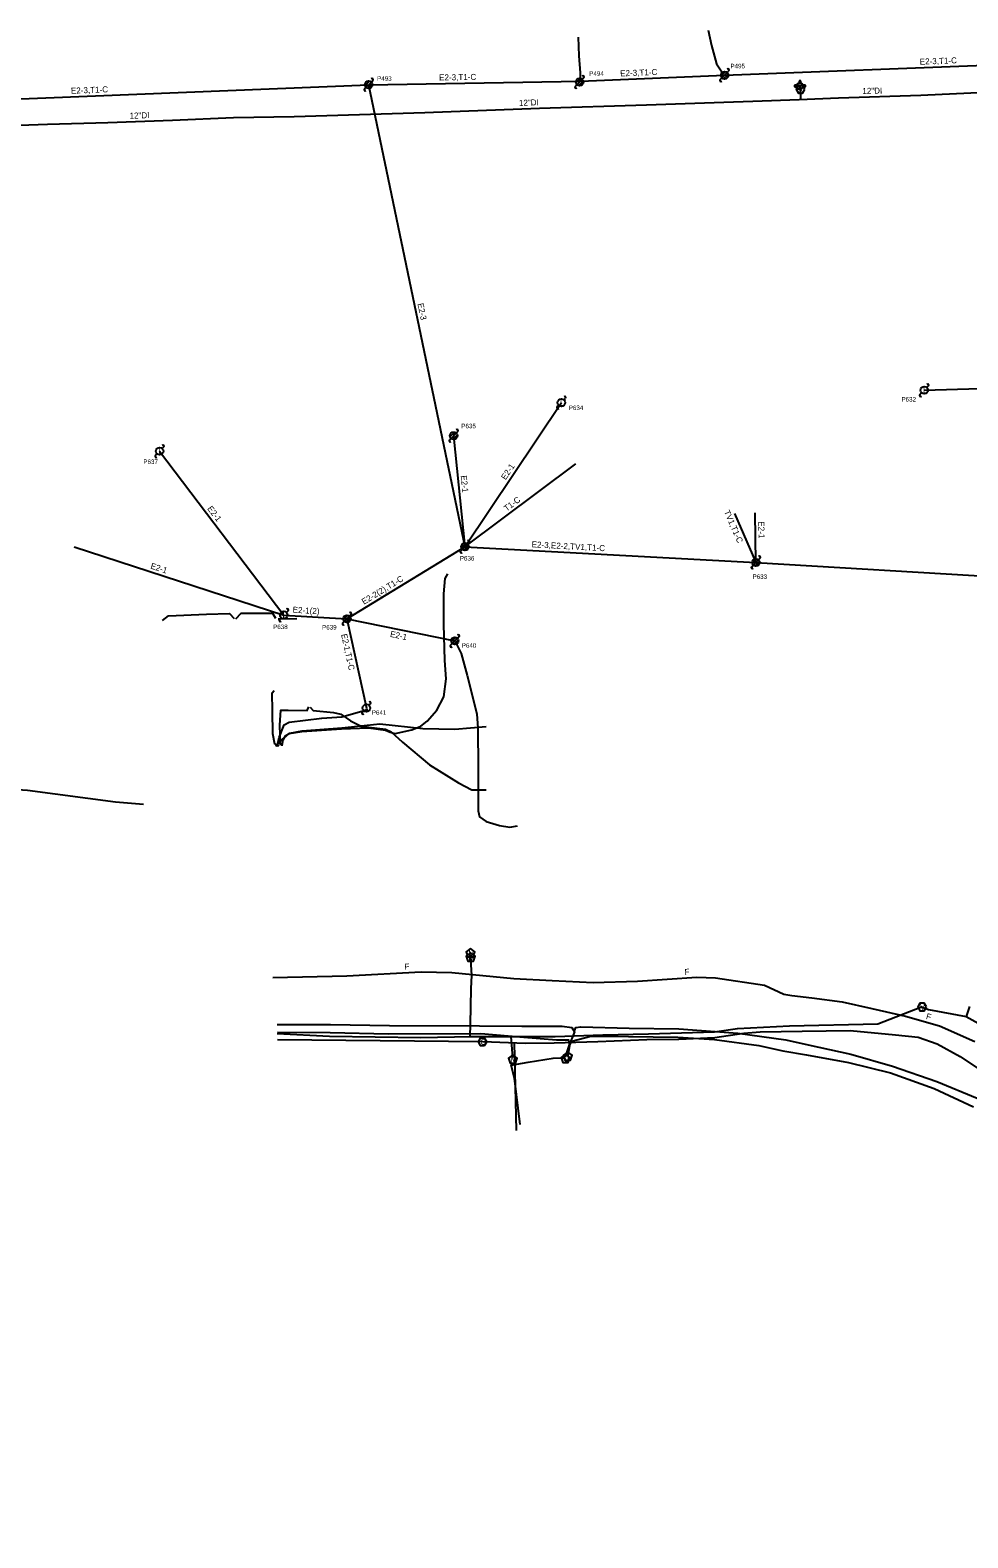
# Model space of a CAD drawing. Extents: x 1741604 to 1825760, y 1164229 to 1194908.
# Drawn here: x 1811075 to 1811697, y 1189297 to 1190297 of the extents above; entities that cross this region are included whole.
import ezdxf

# ---------------------------------------------------------------- set-up
doc = ezdxf.new("R2010")
doc.units = 0
for name, color, linetype in [('RD_EX_SU_Elec', 7, 'Continuous'), ('RD_EX_SU_Gas', 7, 'Continuous'), ('RD_EX_SU_H2O', 7, 'Continuous'), ('RD_EX_SU_Ovhd', 7, 'Continuous'), ('RD_EX_SU_Pole', 7, 'Continuous'), ('RD_EX_SU_Telecom', 7, 'Continuous'), ('RD_EX_SU_TX_H2O', 7, 'Continuous'), ('RD_EX_SU_TX_Pole', 7, 'Continuous'), ('RD_EX_SU_TX_Telecom', 7, 'Continuous')]:
    doc.layers.add(name, color=color, linetype=linetype)

# ---------------------------------------------------------------- blocks, each defined once
blk = doc.blocks.new('SUE_WV')
at = {"layer": 'RD_EX_SU_H2O'}
blk.add_lwpolyline([(2.9, 0), (1.4, 2.5), (-1.4, 2.5), (-2.9, 0), (-1.4, -2.5), (1.4, -2.5)], close=True, dxfattribs=at)
blk.add_text('V', height=3.75, dxfattribs=at).set_placement((-1.4, -1.9))
blk = doc.blocks.new('SUE_WFH')
at = {"layer": 'RD_EX_SU_H2O'}
for p, q in [((-2, 0.6), (-3.6, 0.6)), ((-3.6, 0.6), (-3.6, -0.4)), ((-0.5, 3.4), (-0.5, 2)), ((0.6, 3.4), (-0.5, 3.4)), ((0.6, 2), (0.6, 3.4)), ((3.7, 0.6), (2, 0.6)), ((3.7, -0.4), (3.7, 0.6)), ((-3.6, -0.4), (-2.1, -0.4)), ((2.1, -0.4), (3.7, -0.4))]:
    blk.add_line(p, q, dxfattribs=at)
for radius in [2.1, 0.263]:
    blk.add_circle((0, 0), radius, dxfattribs=at)
for start, end in [(163.3387, 192.315), (74.2455, 103.2128), (347.685, 16.6613)]:
    blk.add_arc((0, 0), 2.1, start, end, dxfattribs=at)
blk = doc.blocks.new('SUE_PP')
at = {"layer": 'RD_EX_SU_Pole'}
for p, q in [((-2.4, -0.6), (0.6, 2.4)), ((-1.8, -1.8), (1.8, 1.8)), ((-0.6, -2.4), (2.4, 0.6)), ((1.8, 1.8), (2.8, 2.8)), ((-2.8, -2.8), (-1.8, -1.8))]:
    blk.add_line(p, q, dxfattribs=at)
blk.add_circle((0, 0), 2.5, dxfattribs=at)
for centre, start, end in [((2.3, 3.4), 315, 135), ((-2.3, -3.4), 135, 315)]:
    blk.add_arc(centre, 0.75, start, end, dxfattribs=at)
blk = doc.blocks.new('SUE_TPP')
at = {"layer": 'RD_EX_SU_Telecom'}
blk.add_lwpolyline([(0, 3), (-2.9, 0.9), (-1.8, -2.4), (1.8, -2.4), (2.9, 0.9)], close=True, dxfattribs=at)
blk.add_text('T', height=3.75, dxfattribs=at).set_placement((-1.3, -1.9))
blk = doc.blocks.new('SUE_GVC')
at = {"layer": 'RD_EX_SU_Gas'}
blk.add_lwpolyline([(1.4, -2.5), (2.9, 0), (1.4, 2.5), (-1.4, 2.5), (-2.9, 0), (-1.4, -2.5)], close=True, dxfattribs=at)
blk.add_text('G', height=3.75, dxfattribs=at).set_placement((-1.3, -1.9))
blk = doc.blocks.new('SUE_WM')
at = {"layer": 'RD_EX_SU_H2O'}
blk.add_lwpolyline([(0, 3.1), (-2.9, 0.9), (-1.8, -2.5), (1.8, -2.5), (2.9, 0.9)], close=True, dxfattribs=at)
blk.add_text('M', height=3.75, dxfattribs=at).set_placement((-1.4, -1.9))
blk = doc.blocks.new('SUE_TVP')
at = {"layer": 'RD_EX_SU_Telecom'}
blk.add_lwpolyline([(0, 3), (-2.9, 0.9), (-1.8, -2.4), (1.8, -2.4), (2.9, 0.9)], close=True, dxfattribs=at)
blk.add_text('C', height=4, dxfattribs=at).set_placement((-1.4, -2))

msp = doc.modelspace()

# ---------------------------------------------------------------- linework, layer by layer
at = {"layer": 'RD_EX_SU_Elec'}
msp.add_line((1811239.6, 1189906.8), (1811252, 1189907), dxfattribs=at)
for points in [[(1811438.7, 1190292.7), (1811439.3, 1190280.4), (1811440.1, 1190269.1), (1811440, 1190264.2)], [(1811162.9, 1189905.5), (1811166.9, 1189908.8), (1811192.2, 1189909.9), (1811207.4, 1189910.3), (1811210.4, 1189906.9)], [(1811211.5, 1189906.8), (1811215.1, 1189910.4), (1811235.9, 1189910.5), (1811237.8, 1189907.1)], [(1811357.2, 1189891.7), (1811361.2, 1189883.8), (1811365.2, 1189869.1), (1811371.4, 1189843.6), (1811372.2, 1189834.2), (1811372.3, 1189807.8), (1811372.5, 1189779.2), (1811373.3, 1189775.4), (1811377.7, 1189772.3), (1811386.5, 1189769.6), (1811393.4, 1189768.4), (1811398.4, 1189769.3)], [(1811240.1, 1189822.3), (1811237.4, 1189823.6), (1811236.2, 1189830.4), (1811235.9, 1189845.7), (1811235.6, 1189857.6), (1811237, 1189859.2)], [(1811238.9, 1189822), (1811240.4, 1189828), (1811243.6, 1189836.3), (1811247, 1189838.2), (1811268.7, 1189840.7), (1811268.7, 1189840.8), (1811281.9, 1189841.7), (1811295.3, 1189845.5), (1811299.2, 1189846.8)], [(1811241.2, 1189822.9), (1811240.8, 1189836.1), (1811241.4, 1189846), (1811246.3, 1189846), (1811258.9, 1189845.9), (1811260.1, 1189848.2)], [(1811260.9, 1189848.1), (1811263, 1189845.8), (1811276.4, 1189844.6), (1811281.2, 1189843.5), (1811287.6, 1189839), (1811295.2, 1189835.3), (1811299.8, 1189834.7), (1811310.8, 1189833.5), (1811314.6, 1189831.7), (1811322.1, 1189824.9), (1811340, 1189809.7), (1811359.4, 1189797.9), (1811368.2, 1189793.3), (1811377.8, 1189793.2)], [(1811242.4, 1189822.5), (1811242.9, 1189826.4), (1811244.6, 1189829.1), (1811247.3, 1189830.9), (1811255.6, 1189832.4), (1811281.9, 1189834.4), (1811307.2, 1189837), (1811335.7, 1189834), (1811356.8, 1189833.5), (1811377.7, 1189835.3)]]:
    msp.add_lwpolyline(points, dxfattribs=at)
at = {"layer": 'RD_EX_SU_Gas'}
for p, q in [((1811239.2, 1189627.6), (1811375.5, 1189626.2)), ((1811396.2, 1189625.4), (1811397.7, 1189567))]:
    msp.add_line(p, q, dxfattribs=at)
for points in [[(1810734.8, 1190009.3), (1810774, 1190011.4), (1810835.1, 1190017.5), (1810866.9, 1190019.3), (1810882.2, 1190019.5), (1810941.5, 1190020.8), (1811000.3, 1190023.5), (1811033.9, 1190028.1), (1811048.1, 1190029.3), (1811051.5, 1190009.5), (1811052.4, 1189991.2), (1811053.5, 1189936.5), (1811055, 1189888.8), (1811056.1, 1189830.6), (1811056.5, 1189794.2), (1811073.4, 1189793), (1811131.7, 1189785.3), (1811150.3, 1189783.6)], [(1811375.5, 1189626.2), (1811403.7, 1189625.1), (1811422.9, 1189625.3), (1811451.9, 1189626.2), (1811484.3, 1189627.4), (1811505.6, 1189627.7), (1811529.5, 1189628.9), (1811548.7, 1189631.8)], [(1811548.7, 1189631.8), (1811559.6, 1189632.5), (1811587.5, 1189633), (1811619.2, 1189633.4), (1811649.4, 1189630.7), (1811664.5, 1189629), (1811677.1, 1189624.6), (1811692.3, 1189616.2), (1811715.1, 1189600.9)]]:
    msp.add_lwpolyline(points, dxfattribs=at)
at = {"layer": 'RD_EX_SU_H2O'}
for p, q in [((1811586.6, 1190251.5), (1811586.2, 1190259.7)), ((1811395.3, 1189615.5), (1811394.4, 1189629.4))]:
    msp.add_line(p, q, dxfattribs=at)
for points in [[(1811043.2, 1190233.5), (1811086.6, 1190235.1), (1811126.7, 1190236.1), (1811169.6, 1190237.6), (1811210.1, 1190239.4), (1811250.3, 1190240.2), (1811337, 1190242.8), (1811413, 1190245.6), (1811484.1, 1190247.9), (1811554.6, 1190250.2), (1811585.4, 1190251.5), (1811611.5, 1190252.6), (1811666.2, 1190254.2), (1811727.8, 1190257.1), (1811744.5, 1190258.3), (1811751, 1190258.5), (1811790.7, 1190260.1), (1811828.8, 1190261.9)], [(1811367.1, 1189629.5), (1811367.3, 1189637.7), (1811367.8, 1189661.2), (1811368.2, 1189670.3), (1811367.4, 1189683.9)], [(1811239, 1189631.5), (1811273.7, 1189629.8), (1811334.4, 1189628.8), (1811367.8, 1189629.5), (1811395.3, 1189629.4), (1811423.5, 1189629.5), (1811455.1, 1189630.7), (1811485.5, 1189631.3), (1811529.3, 1189632.5), (1811544.4, 1189634.8), (1811578.9, 1189636.5), (1811637.6, 1189637.9), (1811666.5, 1189649.2), (1811671.3, 1189647.5), (1811696.3, 1189642.7)], [(1811698.4, 1189649.4), (1811696.3, 1189642.7), (1811716.1, 1189631.6), (1811727.3, 1189624.2), (1811740.2, 1189614.8), (1811756.2, 1189601.7), (1811776.4, 1189587.4), (1811783, 1189583.6), (1811800.8, 1189574.5), (1811834.9, 1189557.1), (1811855.9, 1189546.8), (1811878, 1189532.4), (1811893, 1189521.5), (1811927.7, 1189491.6), (1811968.1, 1189460.6), (1811979, 1189453.4), (1811992.9, 1189443.8), (1812013.5, 1189429.1), (1812036.1, 1189412.4), (1812055.6, 1189396.8), (1812100.9, 1189362.1), (1812129.5, 1189341.4), (1812152.6, 1189324.1), (1812186.1, 1189296.7)]]:
    msp.add_lwpolyline(points, dxfattribs=at)
at = {"layer": 'RD_EX_SU_Ovhd'}
for p, q in [((1811535.9, 1190267.5), (1811787.6, 1190277.2)), ((1811440.4, 1190263.6), (1811535.9, 1190267.5)), ((1810934.5, 1190246.4), (1811299.7, 1190261.2)), ((1811299.7, 1190261.2), (1811440.4, 1190263.6)), ((1811299.7, 1190261.2), (1811363.6, 1189954.6)), ((1811668.4, 1190058.5), (1811753.5, 1190061.2)), ((1811363.6, 1189954.6), (1811427.6, 1190050.2)), ((1811356.1, 1190028.2), (1811363.6, 1189954.6)), ((1811161, 1190018), (1811243.4, 1189909.2)), ((1811363.6, 1189954.6), (1811437.2, 1190009.5)), ((1811542.5, 1189976.7), (1811556.7, 1189944.1)), ((1811556.7, 1189944.1), (1811556.2, 1189977.1)), ((1811104.2, 1189954.4), (1811243.4, 1189909.2)), ((1811285.3, 1189906.7), (1811363.6, 1189954.6)), ((1811363.6, 1189954.6), (1811556.7, 1189944.1)), ((1811556.7, 1189944.1), (1811856.6, 1189926.3)), ((1811243.4, 1189909.2), (1811285.3, 1189906.7)), ((1811285.3, 1189906.7), (1811298.2, 1189847.5)), ((1811285.3, 1189906.7), (1811356.9, 1189892.1))]:
    msp.add_line(p, q, dxfattribs=at)
at = {"layer": 'RD_EX_SU_Pole'}
for p, q in [((1811296.9, 1190258.4), (1811298, 1190259.5)), ((1811297.3, 1190260.6), (1811300.4, 1190263.7)), ((1811298, 1190259.5), (1811301.5, 1190263)), ((1811299.1, 1190258.8), (1811302.2, 1190261.9)), ((1811301.5, 1190263), (1811302.6, 1190264.1)), ((1811665.6, 1190055.6), (1811666.6, 1190056.7)), ((1811670.2, 1190060.2), (1811671.2, 1190061.3)), ((1811424.7, 1190047.4), (1811425.8, 1190048.4)), ((1811429.3, 1190052), (1811430.4, 1190053)), ((1811353.3, 1190025.4), (1811354.4, 1190026.4)), ((1811353.7, 1190027.6), (1811356.8, 1190030.6)), ((1811354.4, 1190026.4), (1811357.9, 1190030)), ((1811355.5, 1190025.8), (1811358.6, 1190028.9)), ((1811357.9, 1190030), (1811359, 1190031)), ((1811158.1, 1190015.1), (1811159.2, 1190016.2)), ((1811162.7, 1190019.7), (1811163.8, 1190020.8)), ((1811361.2, 1189954), (1811364.3, 1189957)), ((1811361.9, 1189952.8), (1811365.4, 1189956.4)), ((1811365.4, 1189956.4), (1811366.4, 1189957.4)), ((1811360.8, 1189951.8), (1811361.9, 1189952.8)), ((1811363, 1189952.2), (1811366, 1189955.2)), ((1811554.3, 1189943.5), (1811557.4, 1189946.6)), ((1811554.9, 1189942.4), (1811558.5, 1189945.9)), ((1811558.5, 1189945.9), (1811559.5, 1189947)), ((1811553.9, 1189941.3), (1811554.9, 1189942.4)), ((1811556.1, 1189941.7), (1811559.1, 1189944.8)), ((1811240.5, 1189906.4), (1811241.6, 1189907.4)), ((1811245.1, 1189911), (1811246.2, 1189912)), ((1811282.9, 1189906.1), (1811285.9, 1189909.1)), ((1811283.5, 1189905), (1811287, 1189908.5)), ((1811284.6, 1189904.3), (1811287.7, 1189907.4)), ((1811287, 1189908.5), (1811288.1, 1189909.5)), ((1811282.4, 1189903.9), (1811283.5, 1189905)), ((1811354.1, 1189889.3), (1811355.1, 1189890.3)), ((1811354.5, 1189891.4), (1811357.6, 1189894.5)), ((1811355.1, 1189890.3), (1811358.7, 1189893.9)), ((1811356.3, 1189889.7), (1811359.3, 1189892.7)), ((1811358.7, 1189893.9), (1811359.7, 1189894.9)), ((1811295.4, 1189844.7), (1811296.4, 1189845.8)), ((1811300, 1189849.3), (1811301, 1189850.4))]:
    msp.add_line(p, q, dxfattribs=at)
for centre in [(1811299.7, 1190261.2), (1811668.4, 1190058.5), (1811427.6, 1190050.2), (1811356.1, 1190028.2), (1811161, 1190018), (1811363.6, 1189954.6), (1811556.7, 1189944.1), (1811243.4, 1189909.2), (1811285.3, 1189906.7), (1811356.9, 1189892.1), (1811298.2, 1189847.5)]:
    msp.add_circle(centre, 2.5, dxfattribs=at)
for centre, start, end in [((1811297.4, 1190257.9), 135, 315), ((1811302, 1190264.6), 315, 135), ((1811666.1, 1190055.1), 135, 315), ((1811670.7, 1190061.8), 315, 135), ((1811425.3, 1190046.9), 135, 315), ((1811429.9, 1190053.6), 315, 135), ((1811358.4, 1190031.6), 315, 135), ((1811163.3, 1190021.3), 315, 135), ((1811353.8, 1190024.9), 135, 315), ((1811158.7, 1190014.6), 135, 315), ((1811365.9, 1189958), 315, 135), ((1811361.3, 1189951.2), 135, 315), ((1811559, 1189947.5), 315, 135), ((1811554.4, 1189940.8), 135, 315), ((1811241.1, 1189905.8), 135, 315), ((1811245.7, 1189912.5), 315, 135), ((1811287.6, 1189910.1), 315, 135), ((1811283, 1189903.4), 135, 315), ((1811359.2, 1189895.4), 315, 135), ((1811354.6, 1189888.7), 135, 315), ((1811300.5, 1189850.9), 315, 135), ((1811295.9, 1189844.2), 135, 315)]:
    msp.add_arc(centre, 0.75, start, end, dxfattribs=at)
at = {"layer": 'RD_EX_SU_Telecom'}
for points in [[(1811525.1, 1190297.4), (1811527.3, 1190287.3), (1811530.6, 1190275.1), (1811535, 1190268.4)], [(1811238.1, 1189822.2), (1811242.2, 1189826.5), (1811247, 1189830.5), (1811255.4, 1189831.9), (1811281.7, 1189833.7), (1811299.7, 1189834.3), (1811310.9, 1189832.9), (1811314.1, 1189831.4), (1811317.3, 1189830.5), (1811328.4, 1189833.1), (1811334.3, 1189835.4), (1811338.6, 1189838.9), (1811345, 1189846.2), (1811349.5, 1189854.9), (1811351.2, 1189866.9), (1811350.2, 1189879.1), (1811349.5, 1189903.1), (1811349.6, 1189923.3), (1811350.4, 1189933.4), (1811352.3, 1189936.5)], [(1811236.1, 1189668.6), (1811285.3, 1189669.7), (1811334.6, 1189672.4), (1811354.9, 1189671.9), (1811396, 1189667.9), (1811421.4, 1189666.7), (1811448.7, 1189665.4), (1811478.1, 1189666.2), (1811517.5, 1189668.8), (1811529.8, 1189668.5), (1811562.5, 1189663.5), (1811575.2, 1189657.7), (1811580.6, 1189656.8)], [(1811580.6, 1189656.8), (1811593.9, 1189655.1), (1811613.9, 1189652.6), (1811633.7, 1189648.1), (1811656, 1189642.9), (1811678.6, 1189636.5), (1811702, 1189626.1)], [(1811239, 1189637.4), (1811274.4, 1189637.4), (1811313.6, 1189636.7), (1811373.3, 1189636.6), (1811401.3, 1189636.4), (1811428.2, 1189636.3), (1811434.6, 1189635.4), (1811436.3, 1189632.7), (1811432.6, 1189623.2), (1811430.2, 1189615.9)], [(1811436.4, 1189633.2), (1811437.3, 1189635.4), (1811440.6, 1189636), (1811472.5, 1189635.1), (1811505.6, 1189634.5), (1811544.8, 1189631.8), (1811576.5, 1189627.2)], [(1811239.3, 1189632.4), (1811274.1, 1189632.1), (1811312.9, 1189631.2), (1811374.2, 1189631.5), (1811402.8, 1189629), (1811424.4, 1189627.2), (1811432.4, 1189627.2), (1811433.1, 1189623.2), (1811431.9, 1189616.9)], [(1811433.1, 1189623.2), (1811434.5, 1189626.5), (1811447.2, 1189629.7), (1811472.2, 1189629.6), (1811505, 1189629.1), (1811529.3, 1189627.5), (1811558.7, 1189623.6), (1811574.5, 1189619.9)], [(1811576.5, 1189627.2), (1811591.3, 1189624), (1811619.7, 1189617.7), (1811647.4, 1189609.8), (1811676.8, 1189599.7), (1811703.6, 1189588.6), (1811713.4, 1189584), (1811714.9, 1189580.5), (1811717.7, 1189575.6), (1811730.6, 1189568.6), (1811748, 1189556.7), (1811765, 1189545.4), (1811783.5, 1189535.1), (1811792.8, 1189528.9), (1811796, 1189524.9), (1811803.9, 1189517.7), (1811814.3, 1189509.3), (1811837.1, 1189490.9), (1811847.4, 1189482.3), (1811854.4, 1189475.5), (1811865, 1189464.7), (1811866.6, 1189462.7), (1811866.3, 1189460.8)], [(1811574.5, 1189619.9), (1811590.2, 1189617.4), (1811618.2, 1189612.2), (1811646, 1189605.3), (1811674.9, 1189594.9), (1811701, 1189582.8)], [(1811400.2, 1189571.1), (1811396.5, 1189601.8), (1811394.4, 1189610.5), (1811405.5, 1189612.4), (1811422.1, 1189615.2), (1811429.5, 1189615.3)]]:
    msp.add_lwpolyline(points, dxfattribs=at)

# ---------------------------------------------------------------- block references
at = {"layer": 'RD_EX_SU_Gas'}
msp.add_blockref('SUE_GVC', (1811375.2, 1189626), dxfattribs=at)
at = {"layer": 'RD_EX_SU_H2O'}
for name, p in [('SUE_WFH', (1811585.9, 1190260.3)), ('SUE_WV', (1811586.3, 1190258.2)), ('SUE_WM', (1811367.3, 1189684.8)), ('SUE_WM', (1811367.4, 1189682)), ('SUE_WV', (1811667, 1189649.1)), ('SUE_WM', (1811395.4, 1189614.2))]:
    msp.add_blockref(name, p, dxfattribs=at)
at = {"layer": 'RD_EX_SU_Pole'}
for p in [(1811439.7, 1190263), (1811535.9, 1190267.5)]:
    msp.add_blockref('SUE_PP', p, dxfattribs=at)
at = {"layer": 'RD_EX_SU_Telecom'}
for name, p in [('SUE_TVP', (1811430.3, 1189614.7)), ('SUE_TPP', (1811431.9, 1189616.1))]:
    msp.add_blockref(name, p, dxfattribs=at)

# ---------------------------------------------------------------- texts
at = {"layer": 'RD_EX_SU_Ovhd'}
for s, rotation, p in [('E2-3,T1-C', 2.2002, (1811665.5, 1190274.5)), ('E2-3,T1-C', 0.9599, (1811346.5, 1190264)), ('E2-3,T1-C', 2.3412, (1811466.7, 1190266.7)), ('E2-3,T1-C', 2.3321, (1811102.2, 1190255.2)), ('E2-3', 281.7676, (1811332.1, 1190115.8)), ('E2-1', 56.2191, (1811390.6, 1189998.6)), ('E2-1', 275.7979, (1811360.8, 1190001.7)), ('T1-C', 36.7625, (1811391.3, 1189977.8)), ('E2-1', 307.1433, (1811192.4, 1189979.8)), ('TV1,T1-C', 293.5902, (1811535.4, 1189977.8)), ('E2-1', 270.9449, (1811558.3, 1189971.4)), ('E2-3,E2-2,TV1,T1-C', 356.8997, (1811407.8, 1189954.2)), ('E2-1', 341.9785, (1811154.6, 1189940.2)), ('E2-2(2),T1-C', 31.4307, (1811296.6, 1189916)), ('E2-1(2)', 356.6313, (1811249.2, 1189910.8)), ('E2-1,T1-C', 282.3224, (1811281.4, 1189896.3)), ('E2-1', 348.4544, (1811313.7, 1189894.8))]:
    msp.add_text(s, height=4, rotation=rotation, dxfattribs=at).set_placement(p)
at = {"layer": 'RD_EX_SU_Pole'}
for p in [(1811667.5, 1190056.5), (1811426.7, 1190048.2), (1811160.1, 1190016), (1811242.5, 1189907.2), (1811297.3, 1189845.5)]:
    msp.add_text('L', height=4, dxfattribs=at).set_placement(p)
at = {"layer": 'RD_EX_SU_TX_H2O'}
for rotation, p in [(1.6706, (1811627.4, 1190255)), (2.1272, (1811399.5, 1190247.1)), (1.9921, (1811141.1, 1190238.6))]:
    msp.add_text('12"DI', height=4, rotation=rotation, dxfattribs=at).set_placement(p)
at = {"layer": 'RD_EX_SU_TX_Pole'}
for s, p in [('P493', (1811305.3, 1190263.8)), ('P494', (1811446.1, 1190267.1)), ('P495', (1811539.8, 1190272.1)), ('P634', (1811432.5, 1190045.3)), ('P632', (1811653.3, 1190050.9)), ('P635', (1811361.2, 1190033.2)), ('P637', (1811150.2, 1190009.5)), ('P636', (1811360.2, 1189945.4)), ('P633', (1811554.5, 1189933.2)), ('P638', (1811236.3, 1189899.9)), ('P639', (1811268.8, 1189899.6)), ('P640', (1811361.5, 1189887.5)), ('P641', (1811301.8, 1189843))]:
    msp.add_text(s, height=3, dxfattribs=at).set_placement(p)
at = {"layer": 'RD_EX_SU_TX_Telecom'}
for rotation, p in [(3.1482, (1811323.6, 1189673.8)), (3.8767, (1811509.5, 1189670.3)), (344.256, (1811669.3, 1189641.2))]:
    msp.add_text('F', height=4, rotation=rotation, dxfattribs=at).set_placement(p)

doc.saveas('drawing.dxf')
